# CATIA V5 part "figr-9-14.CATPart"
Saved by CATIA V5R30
Part number: Part2
Bounding box of the stored display mesh (mm): x -33.329 to 47.777, y -126.495 to 121.369, z -47.545 to 64.906
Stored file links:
  D:\PROJECTS\CATIA V56R 2020\Resources\Parts File\c09_catia_v5_6r2020_prt\figr-9-14.CATPart
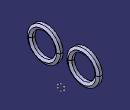
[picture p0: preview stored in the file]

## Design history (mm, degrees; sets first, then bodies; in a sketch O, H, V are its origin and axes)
Body1 (main body)
  Sketch1 on yz-plane, origin (0, 0, 0), H (0, 1, 0), V (0, 0, 1)
    circle A1 centre (-70.2613, 8.6726) radius 37.6716
    circle A2 centre (65.3061, 8.6726) radius 37.5
    radius A2 = 37.5
    radius A1 = 37.6716
  Plane1: type Angle, RefPlane yz-plane, Direction Sketch1.V, Angle 10
  Plane2: type Offset, RefPlane Plane1, Offset 55
  Sketch2 on Plane2, origin (44.5537, 64.0556, 0), H (-0.1736, 0.9848, 0), V (0, 0, 1)
    point P1 (-10.3597, -23.8575)
    point P2 (-2.157, -28.5933)
    point P3 (-2.157, -19.1216)
    point P4 (-10.3597, -14.3858)
    point P5 (-18.5625, -19.1216)
    point P6 (-18.5625, -28.5933)
    point P7 (-10.3597, -33.3292)
    point P8 (-2.157, -23.8575)
    line L1 (-2.157, -28.5933) -> (-2.157, -19.1216)
    line L2 (-2.157, -19.1216) -> (-10.3597, -14.3858)
    line L3 (-10.3597, -14.3858) -> (-18.5625, -19.1216)
    line L4 (-18.5625, -19.1216) -> (-18.5625, -28.5933)
    line L5 (-18.5625, -28.5933) -> (-10.3597, -33.3292)
    line L6 (-10.3597, -33.3292) -> (-2.157, -28.5933)
    construction line L7 (-10.3597, -23.8575) -> (-2.157, -23.8575)
    construction circle A1 centre (-10.3597, -23.8575) radius 9.4717
    construction arc A2 centre (-18.5625, -28.5933) radius 9.4717 from (-18.5625, -19.1216) to (-10.3597, -33.3292) cw
    construction arc A3 centre (-2.157, -19.1216) radius 9.4717 from (-10.3597, -14.3858) to (-2.157, -28.5933) ccw
    horizontal: L7 H
    coincidence: A1 P2, A1 P3, A1 P4, A1 P5, A1 P6, A1 P7, A2 P1, A3 P1
    midpoint: P8 L1
    parallelism: L1 L4
  Rib1: profile Sketch2, centre curve Sketch1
